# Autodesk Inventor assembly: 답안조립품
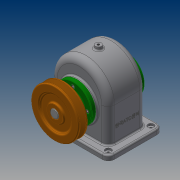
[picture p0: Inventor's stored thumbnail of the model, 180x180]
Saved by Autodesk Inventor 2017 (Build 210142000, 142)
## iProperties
Part Number: 답안조립품
Material: 일반
Document SubType Name: Assembly
Designer: 20
Author: 20
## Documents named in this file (13)
- C:\Users\20\Desktop\480310V1003\답안조립품.iam
- C:\Users\20\Desktop\480310V1003\본체.ipt
- C:\Users\20\Desktop\480310V1003\앞커버.ipt
- C:\Users\20\Desktop\480310V1003\뒤커버.ipt
- C:\Users\20\Desktop\480310V1003\베어링 6203.ipt
- C:\Users\20\Desktop\480310V1003\오일 실 28 40 8.ipt
- C:\Users\20\Desktop\480310V1003\축.ipt
- C:\Users\20\Desktop\480310V1003\키 6x6x22.ipt
- C:\Users\20\Desktop\480310V1003\스퍼기어.ipt
- C:\Users\20\Desktop\480310V1003\키 5x5x18.ipt
- C:\Users\20\Desktop\480310V1003\멈춤나사 M4.ipt
- C:\Users\20\Desktop\480310V1003\V-벨트풀리.ipt
- C:\Users\20\Desktop\480310V1003\볼트 M4.ipt
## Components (1 placed, 1 different names)
1. V-벨트풀리:1
